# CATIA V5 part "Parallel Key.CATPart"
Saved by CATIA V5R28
Part number: Parallel Key
Material "Dark Yellow": density 7860 kg/m3, Young's modulus 2e+11 Pa, Poisson ratio 0.266
Bounding box of the stored display mesh (mm): x -4 to 4, y -56 to 0, z -3.5 to 3.5
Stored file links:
  C:\Users\Parisa\Desktop\tarah sanat\Universal Coupling\Parallel Key.CATPart
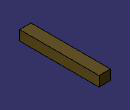
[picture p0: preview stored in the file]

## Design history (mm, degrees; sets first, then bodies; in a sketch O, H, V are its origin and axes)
Body1 "Parallel Key" (main body), material "Dark Yellow"
  Sketch1 on zx-plane, origin (0, 0, 0), H (-1, 0, 0), V (0, 0, 1)
    line L1 (4, 3.5) -> (4, -3.5)
    line L2 (4, -3.5) -> (-4, -3.5)
    line L3 (-4, -3.5) -> (-4, 3.5)
    line L4 (-4, 3.5) -> (4, 3.5)
    length L1 = 7
    length L4 = 8
    vertical: L1 V, L3 V
    horizontal: L2 H, L4 H
    equidistance: L1 L3 O, L2 L4 O
  Pad1: profile Sketch1, direction (0, -1, 0), length 56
